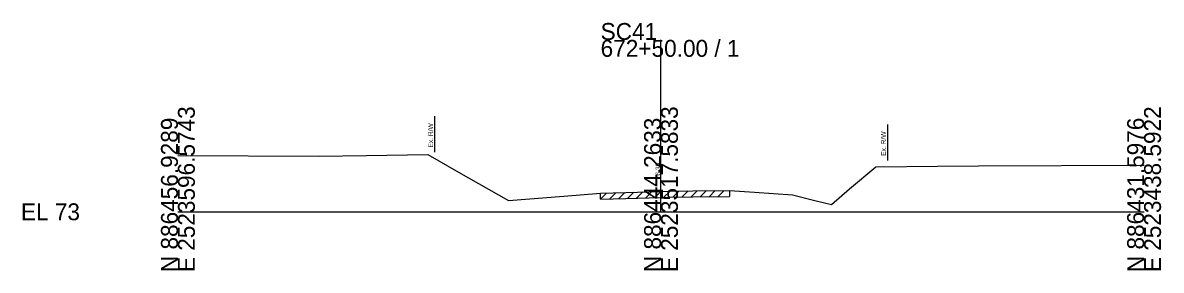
# Model space of a CAD drawing. Extents: x -26 to 183, y -10 to 24021.
# Drawn here: x -25.7 to 162.8, y 4990.3 to 5031.3 of the extents above; entities that cross this region are included whole.
import ezdxf

# ---------------------------------------------------------------- set-up
doc = ezdxf.new("R2010")
doc.units = 0
for name, color, linetype in [('RD_GPK_XS_Cell', 7, 'Continuous'), ('RD_XS_ExGround', 7, 'Continuous'), ('RD_XS_ExPaveRet', 7, 'Continuous'), ('RD_XS_ExRW', 7, 'Continuous'), ('RD_XS_TX_Elev_EX', 7, 'Continuous')]:
    doc.layers.add(name, color=color, linetype=linetype)

msp = doc.modelspace()

# ---------------------------------------------------------------- linework, layer by layer
at = {"layer": 'RD_GPK_XS_Cell'}
for p, q in [((80, 5000), (80, 5028.5)), ((0, 5000), (80, 5000)), ((80, 5000), (160, 5000))]:
    msp.add_line(p, q, dxfattribs=at)
at = {"layer": 'RD_XS_ExGround'}
for p, q in [((0, 5009.33), (23.34, 5009.24)), ((23.34, 5009.24), (31.25, 5009.35)), ((31.25, 5009.35), (41.38, 5009.5)), ((41.38, 5009.5), (46.44, 5006.59)), ((111.23, 5003.79), (115.59, 5007.48)), ((115.59, 5007.48), (125.77, 5007.55)), ((125.77, 5007.55), (132.56, 5007.6)), ((132.56, 5007.6), (160, 5007.75)), ((46.44, 5006.59), (54.74, 5001.89)), ((108.22, 5001.23), (111.23, 5003.79)), ((54.74, 5001.89), (63.89, 5002.6)), ((63.89, 5002.6), (69.97, 5003.07)), ((69.97, 5003.07), (74.15, 5003.2)), ((74.15, 5003.2), (80, 5003.38)), ((80, 5003.38), (81.19, 5003.42)), ((81.19, 5003.42), (85.27, 5003.47)), ((85.27, 5003.47), (91.37, 5003.53)), ((91.37, 5003.53), (95.46, 5003.26)), ((95.46, 5003.26), (101.79, 5002.79)), ((101.79, 5002.79), (105.5, 5001.89)), ((105.5, 5001.89), (108.22, 5001.23))]:
    msp.add_line(p, q, dxfattribs=at)
at = {"layer": 'RD_XS_ExPaveRet'}
for p, q in [((69.97, 5002.07), (71, 5003.1)), ((69.97, 5002.07), (69.97, 5003.07)), ((69.97, 5002.07), (74.15, 5002.2)), ((71.47, 5002.12), (72.5, 5003.15)), ((72.97, 5002.16), (74, 5003.2)), ((74.15, 5002.2), (80, 5002.38)), ((74.47, 5002.21), (75.5, 5003.24)), ((75.97, 5002.26), (77, 5003.29)), ((77.47, 5002.3), (78.5, 5003.34)), ((78.97, 5002.35), (80, 5003.38)), ((80, 5002.38), (81.19, 5002.42)), ((80.47, 5002.4), (81.5, 5003.42)), ((81.19, 5002.42), (85.27, 5002.47)), ((81.97, 5002.43), (82.98, 5003.44)), ((83.47, 5002.44), (84.48, 5003.46)), ((84.97, 5002.46), (85.98, 5003.47)), ((85.27, 5002.47), (91.37, 5002.53)), ((86.47, 5002.48), (87.48, 5003.49)), ((87.97, 5002.49), (88.98, 5003.51)), ((89.47, 5002.51), (90.48, 5003.52)), ((91.37, 5003.53), (91.37, 5002.53))]:
    msp.add_line(p, q, dxfattribs=at)
at = {"layer": 'RD_XS_ExRW'}
for p, q in [((42.5, 5015.86), (42.5, 5009.86)), ((117.5, 5014.49), (117.5, 5008.49))]:
    msp.add_line(p, q, dxfattribs=at)

# ---------------------------------------------------------------- texts
at = {"layer": 'RD_GPK_XS_Cell'}
for s, p in [('SC41', (70, 5028.5)), ('672+50.00 / 1', (70, 5025.7)), ('EL 73', (-26, 4998.6))]:
    msp.add_text(s, height=2.8, dxfattribs=at).set_placement(p)
for s, p in [('E 2523596.5743', (2.8, 4990)), ('E 2523517.5833', (82.8, 4990)), ('E 2523438.5922', (162.8, 4990)), ('N 886456.9289', (0, 4990)), ('N 886444.2633', (80, 4990)), ('N 886431.5976', (160, 4990))]:
    msp.add_text(s, height=2.8, rotation=90, dxfattribs=at).set_placement(p)
at = {"layer": 'RD_XS_ExRW'}
for p in [(42.25, 5010.64), (117.25, 5009.28)]:
    msp.add_text('Ex. R/W ', height=0.8, rotation=90, dxfattribs=at).set_placement(p)
at = {"layer": 'RD_XS_TX_Elev_EX'}
msp.add_text('76.38', height=0.8, rotation=90, dxfattribs=at).set_placement((79.9, 5005.38))

doc.saveas('drawing.dxf')
